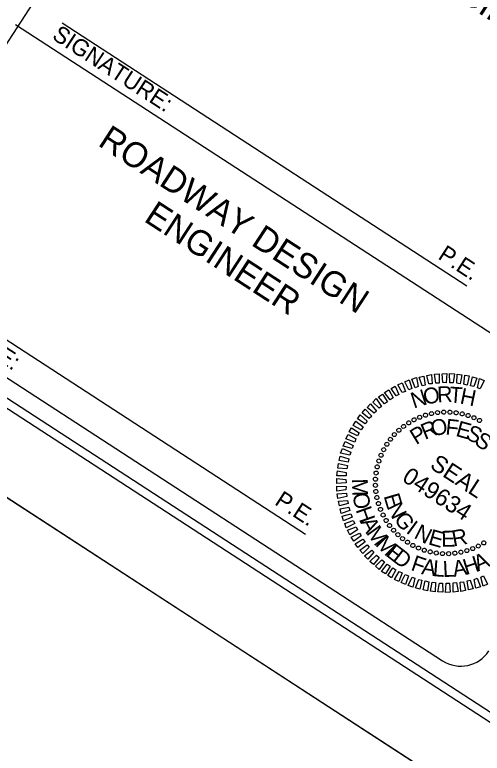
# Model space of a CAD drawing. Extents: x 2291197 to 2302790, y 592892 to 604246.
# Drawn here: x 2298300 to 2298859, y 597328 to 598211 of the extents above; entities that cross this region are included whole.
import ezdxf

# ---------------------------------------------------------------- set-up
doc = ezdxf.new("R2010")
doc.units = 0
for name, color, linetype in [('Default', 7, 'Continuous'), ('Sheet Cutting Line CELL', 7, 'Continuous'), ('Sheet Plot Border Inside CELL', 7, 'Continuous'), ('Sheet Plot Border Outside CELL', 7, 'Continuous'), ('Sheet Professional Seal CELL', 7, 'Continuous'), ('Sheet Title CELL', 7, 'Continuous')]:
    doc.layers.add(name, color=color, linetype=linetype)

# ---------------------------------------------------------------- blocks, each defined once
blk = doc.blocks.new('POINT_DISPLAY')
at = {"layer": 'Default'}
blk.add_line((0, 0), (0, 0), dxfattribs=at)

msp = doc.modelspace()

# ---------------------------------------------------------------- linework, layer by layer
at = {"layer": 'Sheet Cutting Line CELL'}
msp.add_line((2293793.55, 600557.12), (2299441.15, 596885.84), dxfattribs=at)
at = {"layer": 'Sheet Plot Border Inside CELL'}
msp.add_lwpolyline([(2293886.07, 600604.03), (2299474.98, 596970.9), (2301775.2, 600509.37), (2296186.29, 604142.5)], close=True, dxfattribs=at)
at = {"layer": 'Sheet Plot Border Outside CELL'}
msp.add_lwpolyline([(2301839.23, 600574.85), (2296191.63, 604246.13), (2293793.55, 600557.12), (2299441.15, 596885.84)], close=True, dxfattribs=at)
at = {"layer": 'Sheet Professional Seal CELL'}
for points in [[(2298778.93, 597764.96), (2298775.02, 597775.36), (2298780.53, 597777.01), (2298782.67, 597766.36)], [(2298787.34, 597767.35), (2298783.8, 597777.71), (2298789.4, 597778.89), (2298791.07, 597768.14)], [(2298795.32, 597769.41), (2298792.9, 597779.63), (2298798.51, 597780.83), (2298799.29, 597769.65)], [(2298803.68, 597770.21), (2298801.88, 597781.05), (2298807.63, 597781.54), (2298807.66, 597770.44)], [(2298811.92, 597771.1), (2298811.14, 597781.68), (2298816.66, 597782.11), (2298816.13, 597770.78)], [(2298820.39, 597770.82), (2298819.89, 597781.82), (2298825.84, 597781.37), (2298824.18, 597770.78)], [(2298828.68, 597770.27), (2298829.17, 597781.22), (2298834.84, 597780.36), (2298832.72, 597769.66)], [(2298836.94, 597769.33), (2298838.45, 597780.02), (2298843.66, 597779.06), (2298840.97, 597768.11)], [(2298845.29, 597767.32), (2298847.41, 597778.02), (2298852.63, 597776.44), (2298848.9, 597766.38)], [(2298853.37, 597764.89), (2298856.05, 597775.83), (2298861.51, 597773.69), (2298856.8, 597763.67)], [(2298756.11, 597755.24), (2298750.25, 597763.88), (2298755.08, 597766.98), (2298759.55, 597756.83)], [(2298763.46, 597759.11), (2298758.06, 597768.46), (2298763.42, 597770.82), (2298767.33, 597760.43)], [(2298771.33, 597762.25), (2298766.59, 597771.98), (2298771.95, 597774.34), (2298774.78, 597763.83)], [(2298742.36, 597745.86), (2298735.15, 597753.97), (2298739.7, 597757.25), (2298745.71, 597747.91)], [(2298749.19, 597750.48), (2298742.44, 597759.3), (2298747.27, 597762.4), (2298752.63, 597752.67)], [(2298735.96, 597740.36), (2298728.15, 597747.85), (2298732.18, 597751.88), (2298738.88, 597742.68)], [(2298729.85, 597734.66), (2298721.58, 597741.45), (2298725.7, 597745.62), (2298732.77, 597737)], [(2298719.05, 597721.76), (2298709.85, 597727.74), (2298713.26, 597732.36), (2298721.54, 597724.97)], [(2298724.02, 597728.18), (2298715.43, 597734.78), (2298719.12, 597739.23), (2298726.94, 597731.12)], [(2298714.45, 597714.68), (2298704.79, 597719.96), (2298707.91, 597724.76), (2298716.65, 597718.08)], [(2298710.13, 597707.42), (2298700.01, 597711.99), (2298702.85, 597716.98), (2298712.05, 597711)], [(2298706.7, 597699.99), (2298696.13, 597703.85), (2298698.69, 597709.02), (2298708.2, 597703.84)], [(2298703.7, 597692.27), (2298692.95, 597695.24), (2298695.08, 597700.7), (2298704.65, 597695.89)], [(2298700.98, 597684.38), (2298689.86, 597686.78), (2298691.91, 597692.09), (2298701.93, 597688)], [(2298698.98, 597676.02), (2298688, 597677.72), (2298689.16, 597683.21), (2298699.49, 597679.91)], [(2298697.44, 597667.77), (2298686.37, 597668.71), (2298687.25, 597674.39), (2298698.04, 597671.79)], [(2298696.45, 597659.75), (2298685.36, 597659.71), (2298686.22, 597665.39), (2298696.5, 597663.54)], [(2298696.32, 597651.18), (2298685.23, 597650.54), (2298685.21, 597656.39), (2298695.94, 597655.25)], [(2298696.22, 597642.99), (2298685.47, 597641.32), (2298685.45, 597647.17), (2298696.27, 597646.78)], [(2298697.12, 597634.76), (2298686.52, 597632.38), (2298685.8, 597638.09), (2298696.88, 597638.73)], [(2298698.9, 597626.35), (2298688.4, 597623.51), (2298687.21, 597629.12), (2298698.11, 597630.09)], [(2298700.86, 597618.23), (2298690.32, 597614.41), (2298689.14, 597620.01), (2298699.46, 597621.95)], [(2298703.53, 597610.25), (2298693.38, 597605.78), (2298691.49, 597611.24), (2298702.13, 597613.99)], [(2298706.66, 597602.38), (2298696.52, 597597.29), (2298694.68, 597602.52), (2298704.66, 597606.1)], [(2298709.93, 597595.02), (2298700.92, 597589.2), (2298698.1, 597594.46), (2298708.35, 597598.46)], [(2298714.42, 597587.67), (2298705.5, 597581.39), (2298702.41, 597586.22), (2298712.22, 597591.11)], [(2298719.18, 597580.76), (2298710.27, 597573.87), (2298707.27, 597578.23), (2298716.43, 597583.95)], [(2298723.98, 597574.21), (2298716.3, 597566.72), (2298712.74, 597570.85), (2298721.66, 597577.13)], [(2298729.67, 597568.1), (2298722.42, 597559.72), (2298718.25, 597563.84), (2298727.16, 597570.73)], [(2298735.97, 597561.99), (2298728.96, 597553.67), (2298724.65, 597557.27), (2298732.85, 597564.62)], [(2298742.12, 597556.58), (2298735.71, 597547.66), (2298731.51, 597551.4), (2298739, 597559.22)], [(2298749.01, 597551.7), (2298743.32, 597542.32), (2298738.65, 597545.35), (2298745.61, 597553.91)], [(2298755.8, 597547.29), (2298750.82, 597537.44), (2298746.15, 597540.48), (2298752.41, 597549.49)], [(2298763.34, 597543.4), (2298759.24, 597533.37), (2298754.11, 597535.7), (2298759.67, 597545.17)], [(2298770.77, 597539.97), (2298767.38, 597529.49), (2298762.35, 597531.96), (2298767.1, 597541.75)], [(2298778.67, 597537.25), (2298775.99, 597526.31), (2298770.54, 597528.45), (2298775.24, 597538.47)], [(2298853.11, 597537.17), (2298857.02, 597526.78), (2298851.52, 597525.13), (2298849.38, 597535.78)], [(2298860.71, 597539.89), (2298865.45, 597530.16), (2298860.1, 597527.8), (2298857.26, 597538.3)], [(2298786.75, 597534.82), (2298784.63, 597524.12), (2298779.41, 597525.69), (2298783.13, 597535.76)], [(2298795.11, 597532.81), (2298793.59, 597522.11), (2298788.39, 597523.09), (2298791.07, 597534.03)], [(2298803.36, 597531.87), (2298802.88, 597520.91), (2298797.2, 597521.78), (2298799.33, 597532.48)], [(2298811.65, 597531.31), (2298812.15, 597520.32), (2298806.21, 597520.76), (2298807.86, 597531.36)], [(2298820.13, 597531.03), (2298820.9, 597520.46), (2298815.39, 597520.02), (2298815.91, 597531.36)], [(2298828.36, 597531.93), (2298830.17, 597521.09), (2298824.41, 597520.6), (2298824.38, 597531.69)], [(2298836.73, 597532.72), (2298839.14, 597522.5), (2298833.53, 597521.31), (2298832.75, 597532.5)], [(2298844.71, 597534.79), (2298848.25, 597524.44), (2298842.64, 597523.24), (2298840.97, 597533.99)]]:
    msp.add_lwpolyline(points, close=True, dxfattribs=at)
for centre, major_axis in [((2298784.34, 597729.62), (-0.91, 2.25)), ((2298791.31, 597732.08), (-0.71, 2.32)), ((2298798.46, 597733.92), (-0.5, 2.38)), ((2298805.74, 597735.14), (-0.3, 2.41)), ((2298813.11, 597735.72), (-0.08, 2.43)), ((2298820.49, 597735.65), (0.13, 2.43)), ((2298827.84, 597734.94), (0.34, 2.41)), ((2298835.1, 597733.59), (0.55, 2.37)), ((2298842.22, 597731.61), (0.75, 2.31)), ((2298849.14, 597729.02), (0.95, 2.24)), ((2298771.19, 597722.92), (-1.29, 2.06)), ((2298777.62, 597726.56), (-1.1, 2.17)), ((2298855.8, 597725.84), (1.14, 2.15)), ((2298759.4, 597714.05), (-1.63, 1.81)), ((2298765.1, 597718.74), (-1.46, 1.94)), ((2298749.33, 597703.26), (-1.91, 1.5)), ((2298754.13, 597708.87), (-1.78, 1.66)), ((2298745.04, 597697.25), (-2.04, 1.32)), ((2298738.11, 597684.22), (-2.24, 0.95)), ((2298741.29, 597690.88), (-2.15, 1.14)), ((2298735.52, 597677.3), (-2.31, 0.75)), ((2298733.54, 597670.19), (-2.37, 0.55)), ((2298732.19, 597662.93), (-2.41, 0.34)), ((2298731.48, 597655.57), (-2.43, 0.13)), ((2298731.41, 597648.19), (-2.43, -0.08)), ((2298731.99, 597640.83), (-2.41, -0.3)), ((2298733.2, 597633.54), (-2.38, -0.5)), ((2298735.05, 597626.39), (-2.32, -0.71)), ((2298737.51, 597619.43), (-2.25, -0.91)), ((2298740.57, 597612.7), (-2.17, -1.1)), ((2298744.2, 597606.27), (-2.06, -1.29)), ((2298748.39, 597600.19), (-1.94, -1.46)), ((2298753.08, 597594.48), (-1.81, -1.63)), ((2298758.25, 597589.21), (-1.66, -1.78)), ((2298763.87, 597584.41), (-1.5, -1.91)), ((2298769.88, 597580.12), (-1.32, -2.04)), ((2298860.85, 597579.29), (1.29, -2.06)), ((2298776.24, 597576.37), (-1.14, -2.15)), ((2298782.91, 597573.19), (-0.95, -2.24)), ((2298789.82, 597570.6), (-0.75, -2.31)), ((2298840.74, 597570.13), (0.71, -2.32)), ((2298847.7, 597572.59), (0.91, -2.25)), ((2298854.42, 597575.65), (1.1, -2.17)), ((2298796.94, 597568.62), (-0.55, -2.37)), ((2298804.2, 597567.27), (-0.34, -2.41)), ((2298811.55, 597566.56), (-0.13, -2.43)), ((2298818.94, 597566.49), (0.08, -2.43)), ((2298826.3, 597567.07), (0.3, -2.41)), ((2298833.59, 597568.29), (0.5, -2.38))]:
    msp.add_ellipse(centre, major_axis=major_axis, ratio=0.999708, dxfattribs=at)
at = {"layer": 'Sheet Title CELL'}
for p, q in [((2298129.85, 597929.05), (2298478.66, 598465.63)), ((2298301.32, 598199.42), (2299041.37, 597718.34)), ((2298356.94, 598201.36), (2298840.71, 597886.89)), ((2298173.11, 597898.36), (2298647.63, 597589.83))]:
    msp.add_line(p, q, dxfattribs=at)
for points in [[(2294441.63, 600255.04), (2299405.08, 597028.5)], [(2298141.61, 597873.75), (2298811.59, 597438.22)]]:
    msp.add_lwpolyline(points, dxfattribs=at)
msp.add_arc((2298833.52, 597471.95), 40, 236.9737, 326.9737, dxfattribs=at)

# ---------------------------------------------------------------- block references
at = {"layer": 'Sheet Professional Seal CELL', "xscale": 207.0597976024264, "yscale": 207.05979760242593, "rotation": -33.025869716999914}
for p in [(2298791.25, 597732.19), (2298798.44, 597733.96), (2298805.73, 597735.26), (2298813.08, 597735.72), (2298820.52, 597735.72), (2298827.88, 597734.96), (2298835.1, 597733.68), (2298842.24, 597731.66), (2298771.14, 597722.92), (2298777.55, 597726.6), (2298784.35, 597729.63), (2298849.15, 597728.98), (2298855.79, 597725.88), (2298759.35, 597714.08), (2298765.05, 597718.83), (2298754.12, 597708.82), (2298744.98, 597697.25), (2298749.31, 597703.29), (2298741.22, 597690.84), (2298738.11, 597684.2), (2298733.41, 597670.15), (2298735.43, 597677.29), (2298731.36, 597648.12), (2298816.02, 597651.07), (2298731.83, 597640.77), (2298733.13, 597633.49), (2298734.9, 597626.3), (2298737.46, 597619.4), (2298740.49, 597612.6), (2298744.17, 597606.19), (2298748.26, 597600.1), (2298753.01, 597594.4), (2298758.27, 597589.17), (2298763.8, 597584.36), (2298769.84, 597580.03), (2298776.25, 597576.27), (2298782.89, 597573.16), (2298847.69, 597572.5), (2298854.49, 597575.53), (2298789.81, 597570.48), (2298796.95, 597568.45), (2298804.17, 597567.18), (2298811.53, 597566.43), (2298818.97, 597566.41), (2298826.32, 597566.88), (2298833.6, 597568.18), (2298840.79, 597569.94)]:
    msp.add_blockref('POINT_DISPLAY', p, dxfattribs=at)

# ---------------------------------------------------------------- texts
at = {"layer": 'Sheet Professional Seal CELL'}
for s, height, rotation, p in [('R', 19.03, 2.99464, (2298805.67, 597747.2)), ('T', 19.03, 355.7939, (2298819.27, 597747.4)), ('N', 19.03, 18.1346, (2298777.3, 597739.84)), ('O', 19.03, 10.19587, (2298790.27, 597744.55)), ('H', 19.03, 348.59361, (2298831.59, 597746.24)), ('R', 19.03, 22.01378, (2298790.51, 597702.51)), ('O', 19.03, 12.65537, (2298799.93, 597706.46)), ('F', 19.03, 353.94116, (2298814.58, 597708.97)), ('E', 19.03, 344.5852, (2298826.49, 597707.46)), ('P', 19.03, 31.37302, (2298780.13, 597696.17)), ('S', 19.03, 335.22974, (2298838.16, 597704.32)), ('S', 19.03, 325.87453, (2298848.53, 597697.98)), ('SEAL', 20.248, 326.97413, (2298795.32, 597669.56)), ('049634', 20.254, 326.97413, (2298762.05, 597654.14)), ('M', 19.03, 271.38483, (2298703.23, 597656.15)), ('O', 19.03, 280.48091, (2298703.83, 597637.68)), ('E', 19.03, 286.25102, (2298741.1, 597635.56)), ('N', 19.03, 295.60809, (2298744.73, 597622.51)), ('H', 19.03, 289.63926, (2298707.61, 597618.97)), ('G', 19.03, 306.47734, (2298752.8, 597607.67)), ('A', 19.03, 297.52328, (2298713.04, 597604.27)), ('M', 19.03, 305.89954, (2298719.93, 597591.32)), ('I', 19.03, 323.67533, (2298767.05, 597592.1)), ('N', 19.03, 333.03052, (2298776.34, 597585.66)), ('E', 19.03, 343.94099, (2298793.59, 597577.92)), ('E', 19.03, 1.09822, (2298810.24, 597574.69)), ('R', 19.03, 10.45554, (2298824.61, 597575.06)), ('M', 19.03, 314.99053, (2298730.45, 597577)), ('E', 19.03, 322.11719, (2298742.86, 597564.7)), ('D', 19.03, 322.11719, (2298750.76, 597558.59)), ('F', 19.03, 341.0569, (2298772.73, 597547.14)), ('H', 19.03, 17.65723, (2298839.65, 597540.74)), ('A', 19.03, 24.85242, (2298854.04, 597544.92)), ('A', 19.03, 350.95755, (2298785.7, 597542.15)), ('L', 19.03, 355.70244, (2298799.6, 597539.66)), ('L', 19.03, 2.66769, (2298812.29, 597538.46)), ('A', 19.03, 9.85296, (2298825.26, 597538.69))]:
    msp.add_text(s, height=height, rotation=rotation, dxfattribs=at).set_placement(p)
at = {"layer": 'Sheet Title CELL'}
for s, height, p in [(' HYDRAULICS ENGINEER', 30, (2298544.27, 598414.64)), ('SIGNATURE:', 19.998, (2298343.61, 598182.88)), ('ROADWAY DESIGN', 29.9976, (2298398.46, 598055.3)), ('ENGINEER', 29.998, (2298453.37, 597964.73)), ('P.E.', 19.998, (2298805.06, 597919.82)), ('SIGNATURE:', 19.998, (2298161.52, 597873.92)), ('P.E.', 19.998, (2298609.79, 597625.94))]:
    msp.add_text(s, height=height, rotation=326.9737, dxfattribs=at).set_placement(p)

doc.saveas('drawing.dxf')
